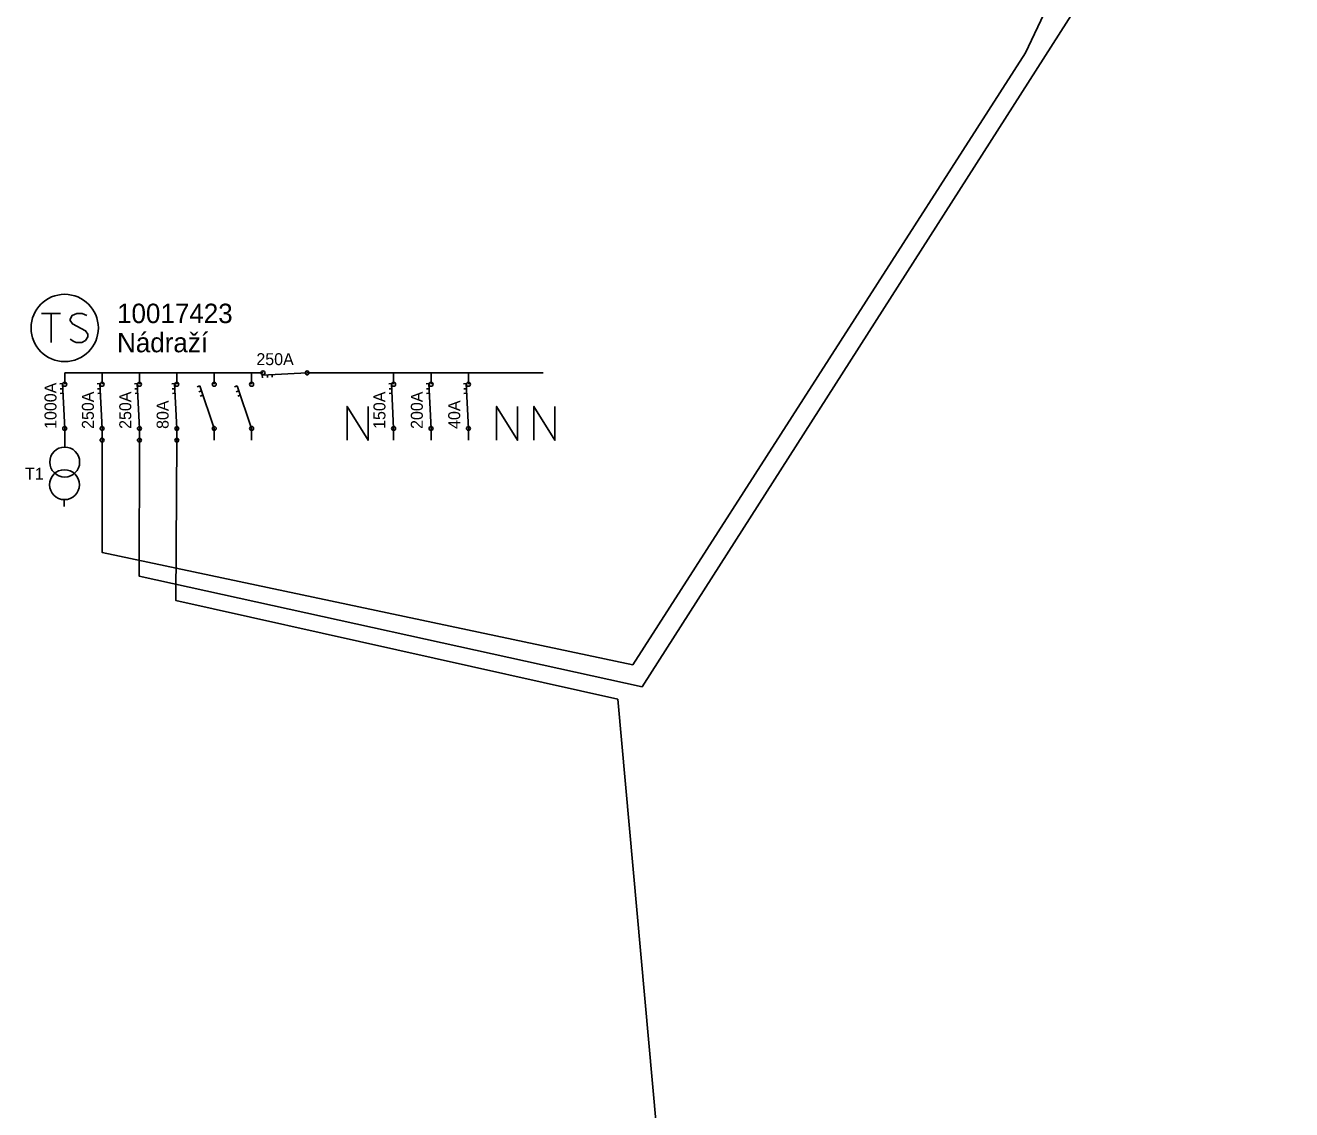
# Model space of a CAD drawing. Extents: x -788474 to -786146, y -1154772 to -1152371.
# Drawn here: x -787328.8 to -787159.5, y -1153518 to -1153373 of the extents above; entities that cross this region are included whole.
import ezdxf

# ---------------------------------------------------------------- set-up
doc = ezdxf.new("R2010")
doc.units = 0
for name, color, linetype in [('Default', 7, 'Continuous'), ('Vrstva 1', 7, 'Continuous'), ('Vrstva 3', 7, 'Continuous')]:
    doc.layers.add(name, color=color, linetype=linetype)

# ---------------------------------------------------------------- blocks, each defined once
blk = doc.blocks.new('STATIO4')
at = {"layer": 'Vrstva 1'}
for p, q in [((-3.11, 1.94), (-0.57, 1.94)), ((-1.82, 1.94), (-1.82, -1.94))]:
    blk.add_line(p, q, dxfattribs=at)
blk.add_lwpolyline([(2.95, 1.67), (2.34, 1.94), (1.64, 1.94), (0.99, 1.67), (0.72, 1.18), (0.72, 0.99), (1.03, 0.54), (2.8, -0.38), (3.11, -0.81), (3.08, -1.18), (2.8, -1.67), (2.28, -1.94), (1.55, -1.94), (1.21, -1.82), (0.72, -1.48)], dxfattribs=at)
blk.add_circle((0, 0), 4.5, dxfattribs=at)
blk = doc.blocks.new('TRAPLC')
at = {"layer": 'Vrstva 1'}
for p, q in [((0, -0.9), (0, 0)), ((-0.07, -8.87), (-0.07, -7.97))]:
    blk.add_line(p, q, dxfattribs=at)
for centre in [(0, -2.93), (-0.03, -5.96)]:
    blk.add_circle(centre, 2, dxfattribs=at)
blk = doc.blocks.new('TAPVN1S1')
at = {"layer": 'Default'}
for p, q in [((0, -1.53), (0, 0)), ((-0.3, -1.43), (-0.65, -1.45)), ((0, -7.44), (-0.3, -1.43)), ((-0.27, -2.12), (-0.62, -2.14)), ((-0.24, -2.74), (-0.59, -2.76)), ((0, -9.01), (0, -7.44))]:
    blk.add_line(p, q, dxfattribs=at)
for centre in [(0, -1.53), (0, -7.44)]:
    blk.add_circle(centre, 0.265, dxfattribs=at)
blk = doc.blocks.new('TAPVN1S2')
at = {"layer": 'Default'}
for p, q in [((0, -1.53), (0, 0)), ((-1.94, -1.74), (-2.27, -1.86)), ((-1.72, -2.4), (-2.05, -2.52)), ((0, -7.44), (-1.94, -1.74)), ((-1.52, -2.99), (-1.86, -3.11)), ((0, -9.01), (0, -7.44))]:
    blk.add_line(p, q, dxfattribs=at)
for centre in [(0, -1.53), (0, -7.44)]:
    blk.add_circle(centre, 0.265, dxfattribs=at)
blk = doc.blocks.new('TAPV2')
at = {"layer": 'Default'}
blk.add_lwpolyline([(-1.23, -9.01), (-1.23, -4.5), (1.57, -9.01), (1.57, -4.5)], dxfattribs=at)
blk = doc.blocks.new('TAPV1')
at = {"layer": 'Vrstva 1'}
blk.add_circle((0, 0), 0.265, dxfattribs=at)

msp = doc.modelspace()

# ---------------------------------------------------------------- linework, layer by layer
at = {"layer": 'Vrstva 1'}
for points in [[(-787159.46, -1153286.94), (-787159.46, -1153311.94), (-787167.16, -1153337.45), (-787188.29, -1153370.62), (-787246.34, -1153461.45), (-787313.62, -1153446.65), (-787313.58, -1153428.48)], [(-787192.19, -1153370.65), (-787195.06, -1153376.68), (-787247.59, -1153458.52), (-787318.59, -1153443.49), (-787318.58, -1153428.48)], [(-787308.58, -1153428.48), (-787308.72, -1153449.92), (-787249.6, -1153463.11)], [(-787249.6, -1153463.11), (-787225.91, -1153725.56)]]:
    msp.add_lwpolyline(points, dxfattribs=at)
at = {"layer": 'Vrstva 3'}
for points in [[(-787323.58, -1153419.48), (-787298.58, -1153419.48)], [(-787289.58, -1153419.48), (-787259.58, -1153419.48)]]:
    msp.add_lwpolyline(points, dxfattribs=at)

# ---------------------------------------------------------------- block references
for name, p in [('STATIO4', (-787323.58, -1153413.48)), ('TAPVN1S1', (-787323.58, -1153419.48)), ('TAPVN1S1', (-787318.58, -1153419.48)), ('TAPVN1S1', (-787313.58, -1153419.48)), ('TAPVN1S1', (-787308.58, -1153419.48)), ('TAPVN1S2', (-787303.58, -1153419.48)), ('TAPVN1S2', (-787298.58, -1153419.48)), ('TAPVN1S1', (-787279.58, -1153419.48)), ('TAPVN1S1', (-787274.58, -1153419.48)), ('TAPVN1S1', (-787269.58, -1153419.48)), ('TAPV2', (-787284.58, -1153419.48)), ('TAPV2', (-787264.58, -1153419.48)), ('TAPV2', (-787259.58, -1153419.48)), ('TRAPLC', (-787323.58, -1153428.48)), ('TAPV1', (-787318.58, -1153428.48)), ('TAPV1', (-787313.58, -1153428.48)), ('TAPV1', (-787308.58, -1153428.48))]:
    msp.add_blockref(name, p, dxfattribs=at)
at = {"layer": 'Vrstva 3', "rotation": 90}
msp.add_blockref('TAPVN1S1', (-787298.58, -1153419.48), dxfattribs=at)

# ---------------------------------------------------------------- texts
at = {"layer": 'Vrstva 3'}
for s, height, p in [('10017423', 2.6, (-787316.58, -1153412.83)), ('Nádraží', 2.6, (-787316.58, -1153416.73)), ('250A', 1.6, (-787297.94, -1153418.45)), ('T1', 1.6, (-787328.89, -1153433.78))]:
    msp.add_text(s, height=height, dxfattribs=at).set_placement(p)
for s, p in [('1000A', (-787324.68, -1153426.98)), ('250A', (-787319.68, -1153426.98)), ('250A', (-787314.68, -1153426.98)), ('80A', (-787309.68, -1153426.98)), ('150A', (-787280.68, -1153426.98)), ('200A', (-787275.68, -1153426.98)), ('40A', (-787270.68, -1153426.98))]:
    msp.add_text(s, height=1.6, rotation=90, dxfattribs=at).set_placement(p)

doc.saveas('drawing.dxf')
